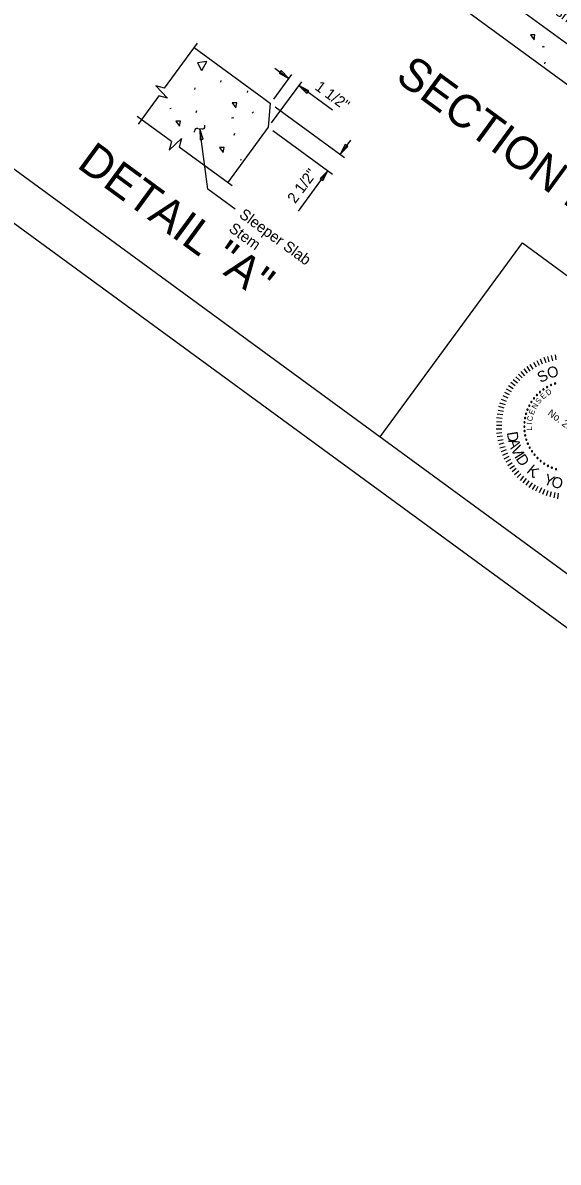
# Model space of a CAD drawing. Extents: x 1970731 to 1970899, y 796145 to 796301.
# Drawn here: x 1970789.2 to 1970813.6, y 796145.2 to 796197.4 of the extents above; entities that cross this region are included whole.
import ezdxf

# ---------------------------------------------------------------- set-up
doc = ezdxf.new("R2010")
doc.units = 0
for name, color, linetype in [('BR_AUTO DIMENSION', 7, 'Continuous'), ('BR_BORDER LINES', 7, 'Continuous'), ('BR_CONCRETE', 7, 'Continuous'), ('BR_DETAILS', 7, 'Continuous'), ('BR_TEXT', 7, 'Continuous'), ('Level 31', 7, 'Continuous')]:
    doc.layers.add(name, color=color, linetype=linetype)

msp = doc.modelspace()

# ---------------------------------------------------------------- linework, layer by layer
at = {"layer": 'BR_AUTO DIMENSION'}
for p, q in [((1970800.627, 796193.871), (1970801.45, 796194.996)), ((1970800.674, 796195.29), (1970801.32, 796194.818)), ((1970800.527, 796192.782), (1970801.904, 796194.663)), ((1970803.315, 796193.357), (1970801.774, 796194.485)), ((1970800.681, 796193.522), (1970803.857, 796191.196)), ((1970797.613, 796189.742), (1970797.246, 796192.514)), ((1970800.581, 796192.433), (1970803.303, 796190.44)), ((1970804.128, 796191.99), (1970803.655, 796191.344)), ((1970801.75, 796188.742), (1970803.101, 796190.588)), ((1970798.858, 796188.831), (1970797.613, 796189.742))]:
    msp.add_line(p, q, dxfattribs=at)
for points in [[(1970800.872, 796195.052), (1970801.32, 796194.818), (1970800.961, 796195.173)], [(1970802.222, 796194.25), (1970801.774, 796194.485), (1970802.133, 796194.129)], [(1970797.4, 796192.032), (1970797.246, 796192.514), (1970797.252, 796192.009)], [(1970803.89, 796191.792), (1970803.655, 796191.344), (1970804.011, 796191.703)], [(1970802.867, 796190.14), (1970803.101, 796190.588), (1970802.746, 796190.229)]]:
    msp.add_lwpolyline(points, close=True, dxfattribs=at)
at = {"layer": 'BR_BORDER LINES'}
for p, q in [((1970738.359, 796227.562), (1970847.014, 796148.01)), ((1970805.492, 796178.411), (1970811.99, 796187.287)), ((1970811.99, 796187.287), (1970829.306, 796174.609))]:
    msp.add_line(p, q, dxfattribs=at)
at = {"layer": 'BR_CONCRETE'}
for p, q in [((1970827.934, 796186.216), (1970803.754, 796203.919)), ((1970827.073, 796184.987), (1970802.867, 796202.709)), ((1970827.073, 796184.987), (1970802.867, 796202.709)), ((1970796.989, 796196.224), (1970800.177, 796193.891)), ((1970800.177, 796193.891), (1970800.479, 796193.669)), ((1970800.379, 796192.581), (1970800.479, 796193.669)), ((1970798.521, 796190.042), (1970800.379, 796192.581))]:
    msp.add_line(p, q, dxfattribs=at)
at = {"layer": 'BR_DETAILS'}
for p, q in [((1970795.631, 796194.369), (1970797.137, 796196.426)), ((1970812.953, 796196.27), (1970812.897, 796196.25)), ((1970812.991, 796196.266), (1970812.935, 796196.245)), ((1970813.023, 796195.478), (1970813.04, 796195.558)), ((1970798.198, 796194.642), (1970798.215, 796194.722)), ((1970795.374, 796194.018), (1970794.429, 796192.728)), ((1970797.016, 796194.31), (1970797.033, 796194.391)), ((1970799.42, 796194.17), (1970799.438, 796194.25)), ((1970795.928, 796193.445), (1970795.872, 796193.424)), ((1970795.946, 796191.927), (1970794.375, 796193.077)), ((1970797.082, 796193.26), (1970797.1, 796193.34)), ((1970798.751, 796193.016), (1970798.695, 796192.996)), ((1970798.789, 796193.012), (1970798.733, 796192.991)), ((1970799.695, 796193.287), (1970799.644, 796193.231)), ((1970797.004, 796192.354), (1970797.002, 796192.405)), ((1970797.146, 796192.529), (1970797.349, 796192.503)), ((1970797.472, 796192.615), (1970797.473, 796192.683)), ((1970798.821, 796192.224), (1970798.839, 796192.304)), ((1970798.723, 796189.894), (1970796.297, 796191.671)), ((1970799.146, 796191.089), (1970799.089, 796191.068))]:
    msp.add_line(p, q, dxfattribs=at)
for points in [[(1970812.526, 796196.58), (1970812.568, 796196.807), (1970812.36, 796196.804), (1970812.526, 796196.58)], [(1970797.33, 796195.171), (1970797.557, 796195.594), (1970797.135, 796195.522), (1970797.325, 796195.178)], [(1970795.631, 796194.369), (1970795.234, 796194.48), (1970795.771, 796193.907), (1970795.374, 796194.018)], [(1970798.89, 796193.474), (1970798.933, 796193.701), (1970798.725, 796193.699), (1970798.89, 796193.474)], [(1970796.311, 796192.635), (1970796.353, 796192.862), (1970796.145, 796192.859), (1970796.311, 796192.635)], [(1970795.946, 796191.927), (1970795.835, 796191.53), (1970796.408, 796192.067), (1970796.297, 796191.671)], [(1970798.312, 796191.43), (1970798.355, 796191.657), (1970798.147, 796191.655), (1970798.312, 796191.43)]]:
    msp.add_lwpolyline(points, dxfattribs=at)
for centre, radius, start, end in [((1970797.118, 796192.417), 0.116, 76.1551, 185.954), ((1970797.37, 796192.602), 0.103, 258.6, 6.8856)]:
    msp.add_arc(centre, radius, start, end, dxfattribs=at)
at = {"layer": 'BR_TEXT'}
for p, q in [((1970812.917, 796181.741), (1970812.819, 796181.972)), ((1970813.082, 796181.802), (1970812.987, 796182.036)), ((1970813.221, 796181.845), (1970813.155, 796182.09)), ((1970813.383, 796181.89), (1970813.316, 796182.133)), ((1970813.539, 796181.933), (1970813.499, 796182.172)), ((1970812.23, 796181.324), (1970812.069, 796181.517)), ((1970812.354, 796181.411), (1970812.209, 796181.63)), ((1970812.489, 796181.512), (1970812.353, 796181.72)), ((1970812.637, 796181.595), (1970812.512, 796181.812)), ((1970812.78, 796181.672), (1970812.664, 796181.896)), ((1970811.773, 796180.873), (1970811.567, 796181.026)), ((1970811.876, 796180.993), (1970811.694, 796181.163)), ((1970811.988, 796181.115), (1970811.811, 796181.285)), ((1970812.107, 796181.206), (1970811.943, 796181.405)), ((1970811.404, 796180.33), (1970811.186, 796180.446)), ((1970811.488, 796180.473), (1970811.272, 796180.596)), ((1970811.572, 796180.603), (1970811.362, 796180.751)), ((1970811.669, 796180.745), (1970811.468, 796180.894)), ((1970811.214, 796179.881), (1970810.965, 796179.96)), ((1970811.264, 796180.028), (1970811.033, 796180.127)), ((1970811.342, 796180.179), (1970811.109, 796180.285)), ((1970811.096, 796179.412), (1970810.843, 796179.451)), ((1970811.127, 796179.569), (1970810.877, 796179.618)), ((1970811.16, 796179.728), (1970810.922, 796179.799)), ((1970811.052, 796179.077), (1970810.803, 796179.104)), ((1970811.051, 796178.932), (1970810.803, 796178.933)), ((1970811.063, 796179.253), (1970810.814, 796179.28)), ((1970811.054, 796178.763), (1970810.8, 796178.756)), ((1970811.054, 796178.596), (1970810.815, 796178.569)), ((1970811.086, 796178.444), (1970810.834, 796178.405)), ((1970811.107, 796178.278), (1970810.862, 796178.23)), ((1970811.151, 796178.118), (1970810.908, 796178.062)), ((1970811.197, 796177.955), (1970810.955, 796177.895)), ((1970811.244, 796177.812), (1970811.02, 796177.718)), ((1970811.304, 796177.657), (1970811.076, 796177.557)), ((1970811.367, 796177.511), (1970811.148, 796177.396)), ((1970811.444, 796177.368), (1970811.234, 796177.247)), ((1970811.527, 796177.221), (1970811.323, 796177.09)), ((1970811.625, 796177.088), (1970811.414, 796176.954)), ((1970811.712, 796176.963), (1970811.526, 796176.806)), ((1970811.828, 796176.843), (1970811.633, 796176.68)), ((1970811.928, 796176.713), (1970811.758, 796176.548)), ((1970812.044, 796176.605), (1970811.883, 796176.417)), ((1970812.165, 796176.502), (1970812.017, 796176.304)), ((1970812.293, 796176.393), (1970812.148, 796176.198)), ((1970812.434, 796176.301), (1970812.292, 796176.099)), ((1970812.57, 796176.213), (1970812.436, 796176.005)), ((1970812.704, 796176.134), (1970812.598, 796175.923)), ((1970812.86, 796176.074), (1970812.756, 796175.843)), ((1970813.008, 796175.997), (1970812.917, 796175.771)), ((1970813.156, 796175.948), (1970813.085, 796175.709)), ((1970813.311, 796175.892), (1970813.244, 796175.659)), ((1970813.468, 796175.861), (1970813.422, 796175.616)), ((1970813.624, 796175.83), (1970813.59, 796175.577))]:
    msp.add_line(p, q, dxfattribs=at)
for centre, start, end in [((1970812.797, 796180.461), 40.8559, 220.8559), ((1970812.797, 796180.461), 220.8559, 40.8559), ((1970812.954, 796180.584), 35.3174, 215.3174), ((1970812.954, 796180.584), 215.3174, 35.3174), ((1970813.122, 796180.69), 29.779, 209.779), ((1970813.122, 796180.69), 209.779, 29.779), ((1970813.3, 796180.781), 24.2405, 204.2405), ((1970813.3, 796180.781), 204.2405, 24.2405), ((1970813.486, 796180.853), 18.702, 198.702), ((1970813.486, 796180.853), 198.702, 18.702), ((1970812.307, 796179.838), 63.0097, 243.0097), ((1970812.406, 796180.011), 57.4713, 237.4713), ((1970812.406, 796180.011), 237.4713, 57.4713), ((1970812.522, 796180.173), 51.9328, 231.9328), ((1970812.522, 796180.173), 231.9328, 51.9328), ((1970812.652, 796180.324), 46.3943, 226.3943), ((1970812.652, 796180.324), 226.3943, 46.3943), ((1970812.161, 796179.468), 74.0866, 254.0866), ((1970812.161, 796179.468), 254.0866, 74.0866), ((1970812.225, 796179.656), 68.5482, 248.5482), ((1970812.225, 796179.656), 248.5482, 68.5482), ((1970812.307, 796179.838), 243.0097, 63.0097), ((1970812.08, 796178.877), 90.702, 270.702), ((1970812.088, 796179.076), 85.1636, 265.1636), ((1970812.08, 796178.877), 270.702, 90.702), ((1970812.088, 796179.076), 265.1636, 85.1636), ((1970812.115, 796179.274), 79.6251, 259.6251), ((1970812.115, 796179.274), 259.6251, 79.6251), ((1970812.092, 796178.678), 96.2405, 276.2405), ((1970812.092, 796178.678), 276.2405, 96.2405), ((1970812.123, 796178.481), 101.779, 281.779), ((1970812.123, 796178.481), 281.779, 101.779), ((1970812.173, 796178.288), 107.3174, 287.3174), ((1970812.173, 796178.288), 287.3174, 107.3174), ((1970812.241, 796178.101), 112.8559, 292.8559), ((1970812.241, 796178.101), 292.8559, 112.8559), ((1970812.327, 796177.921), 118.3943, 298.3943), ((1970812.327, 796177.921), 298.3943, 118.3943), ((1970812.429, 796177.75), 123.9328, 303.9328), ((1970812.429, 796177.75), 303.9328, 123.9328), ((1970812.548, 796177.59), 129.4713, 309.4713), ((1970812.548, 796177.59), 309.4713, 129.4713), ((1970812.682, 796177.442), 135.0097, 315.0097), ((1970812.682, 796177.442), 315.0097, 135.0097), ((1970812.829, 796177.308), 140.5482, 320.5482), ((1970812.829, 796177.308), 320.5482, 140.5482), ((1970812.989, 796177.188), 146.0866, 326.0866), ((1970812.989, 796177.188), 326.0866, 146.0866), ((1970813.159, 796177.085), 151.6251, 331.6251), ((1970813.159, 796177.085), 331.6251, 151.6251), ((1970813.339, 796176.999), 157.1636, 337.1636), ((1970813.339, 796176.999), 337.1636, 157.1636), ((1970813.526, 796176.93), 162.702, 342.702), ((1970813.526, 796176.93), 342.702, 162.702)]:
    msp.add_arc(centre, 0.028, start, end, dxfattribs=at)
at = {"layer": 'Level 31'}
msp.add_lwpolyline([(1970731.261, 796230.28), (1970847.449, 796145.214), (1970899.434, 796216.218), (1970783.245, 796301.284)], close=True, dxfattribs=at)

# ---------------------------------------------------------------- texts
at = {"layer": 'BR_AUTO DIMENSION'}
msp.add_text('2 1/2"', height=0.5, rotation=53.7906, dxfattribs=at).set_placement((1970801.604, 796189.056))
at = {"layer": 'BR_TEXT'}
for s, height, rotation, p in [('Reinforcing not shown. ', 0.49995, 323.7906, (1970809.688, 796200.537)), ('SECTION D-D', 1.5, 323.7906, (1970806.131, 796194.749)), ('1 1/2"', 0.4999, 323.7906, (1970802.467, 796194.336)), ('DETAIL "A"', 1.5, 323.7906, (1970791.573, 796190.774)), ('Sleeper Slab', 0.49995, 323.7906, (1970799.003, 796188.496)), ('Stem', 0.4999, 323.7906, (1970798.53, 796187.851)), ('S', 0.496, 27.0417, (1970812.827, 796180.869)), ('O', 0.496, 15.8173, (1970813.199, 796181.07)), ('E', 0.249, 42.0294, (1970812.943, 796180.112)), ('D', 0.249, 32.827, (1970813.154, 796180.288)), ('N', 0.249, 61.1237, (1970812.609, 796179.653)), ('S', 0.249, 51.5766, (1970812.756, 796179.896)), ('C', 0.249, 80.2172, (1970812.443, 796179.109)), ('E', 0.249, 70.3261, (1970812.506, 796179.398)), ('No. 29964', 0.327, 323.3174, (1970813.121, 796179.439)), ('I', 0.249, 84.8917, (1970812.431, 796178.97)), ('L', 0.249, 93.7501, (1970812.439, 796178.706)), ('D', 0.494, 279.1958, (1970811.277, 796178.611)), ('A', 0.494, 286.6283, (1970811.337, 796178.242)), ('V', 0.494, 294.3085, (1970811.448, 796177.872)), ('I', 0.494, 301.9887, (1970811.608, 796177.52)), ('D', 0.494, 304.5901, (1970811.673, 796177.406)), ('K', 0.494, 319.8885, (1970812.151, 796176.805)), ('.', 0.494, 326.9494, (1970812.422, 796176.576)), ('Y', 0.494, 338.6555, (1970812.927, 796176.273)), ('O', 0.494, 346.2118, (1970813.281, 796176.135))]:
    msp.add_text(s, height=height, rotation=rotation, dxfattribs=at).set_placement(p)

doc.saveas('drawing.dxf')
